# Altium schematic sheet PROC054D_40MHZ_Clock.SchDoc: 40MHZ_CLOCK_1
size 558 x 431 mm; Date: Not shown in title block; ApprovedBy: Not shown in title block; CheckedBy: Not shown in title block; Author: Not shown in title block; CompanyName: Not shown in title block; DrawnBy: a0271760; Engineer: Not shown in title block; Organization: Not shown in title block; Address1: Not shown in title block; Address2: Not shown in title block; Address3: Not shown in title block; Address4: Not shown in title block; DocumentNumber: 13; Revision: Use project pAWRameter SCH_Rev; SheetNumber: 13; SheetTotal: 19; PageSetup: Record=PageOptions¦CenterHorizontal=True¦CenterVertical=True¦PrintScale=1.00¦XCorrection=1.00¦YCorrection=1.00¦PrintKind=0¦BorderSize=5000000¦LeftOffset=0¦BottomOffset=0¦Orientation=2¦PaperLength=1000¦PaperWidth=1000¦Scale=100¦PaperSource=15¦PrintQuality=600¦MediaType=1¦DitherType=10¦PaperKind=Letter¦PrintScaleMode=1
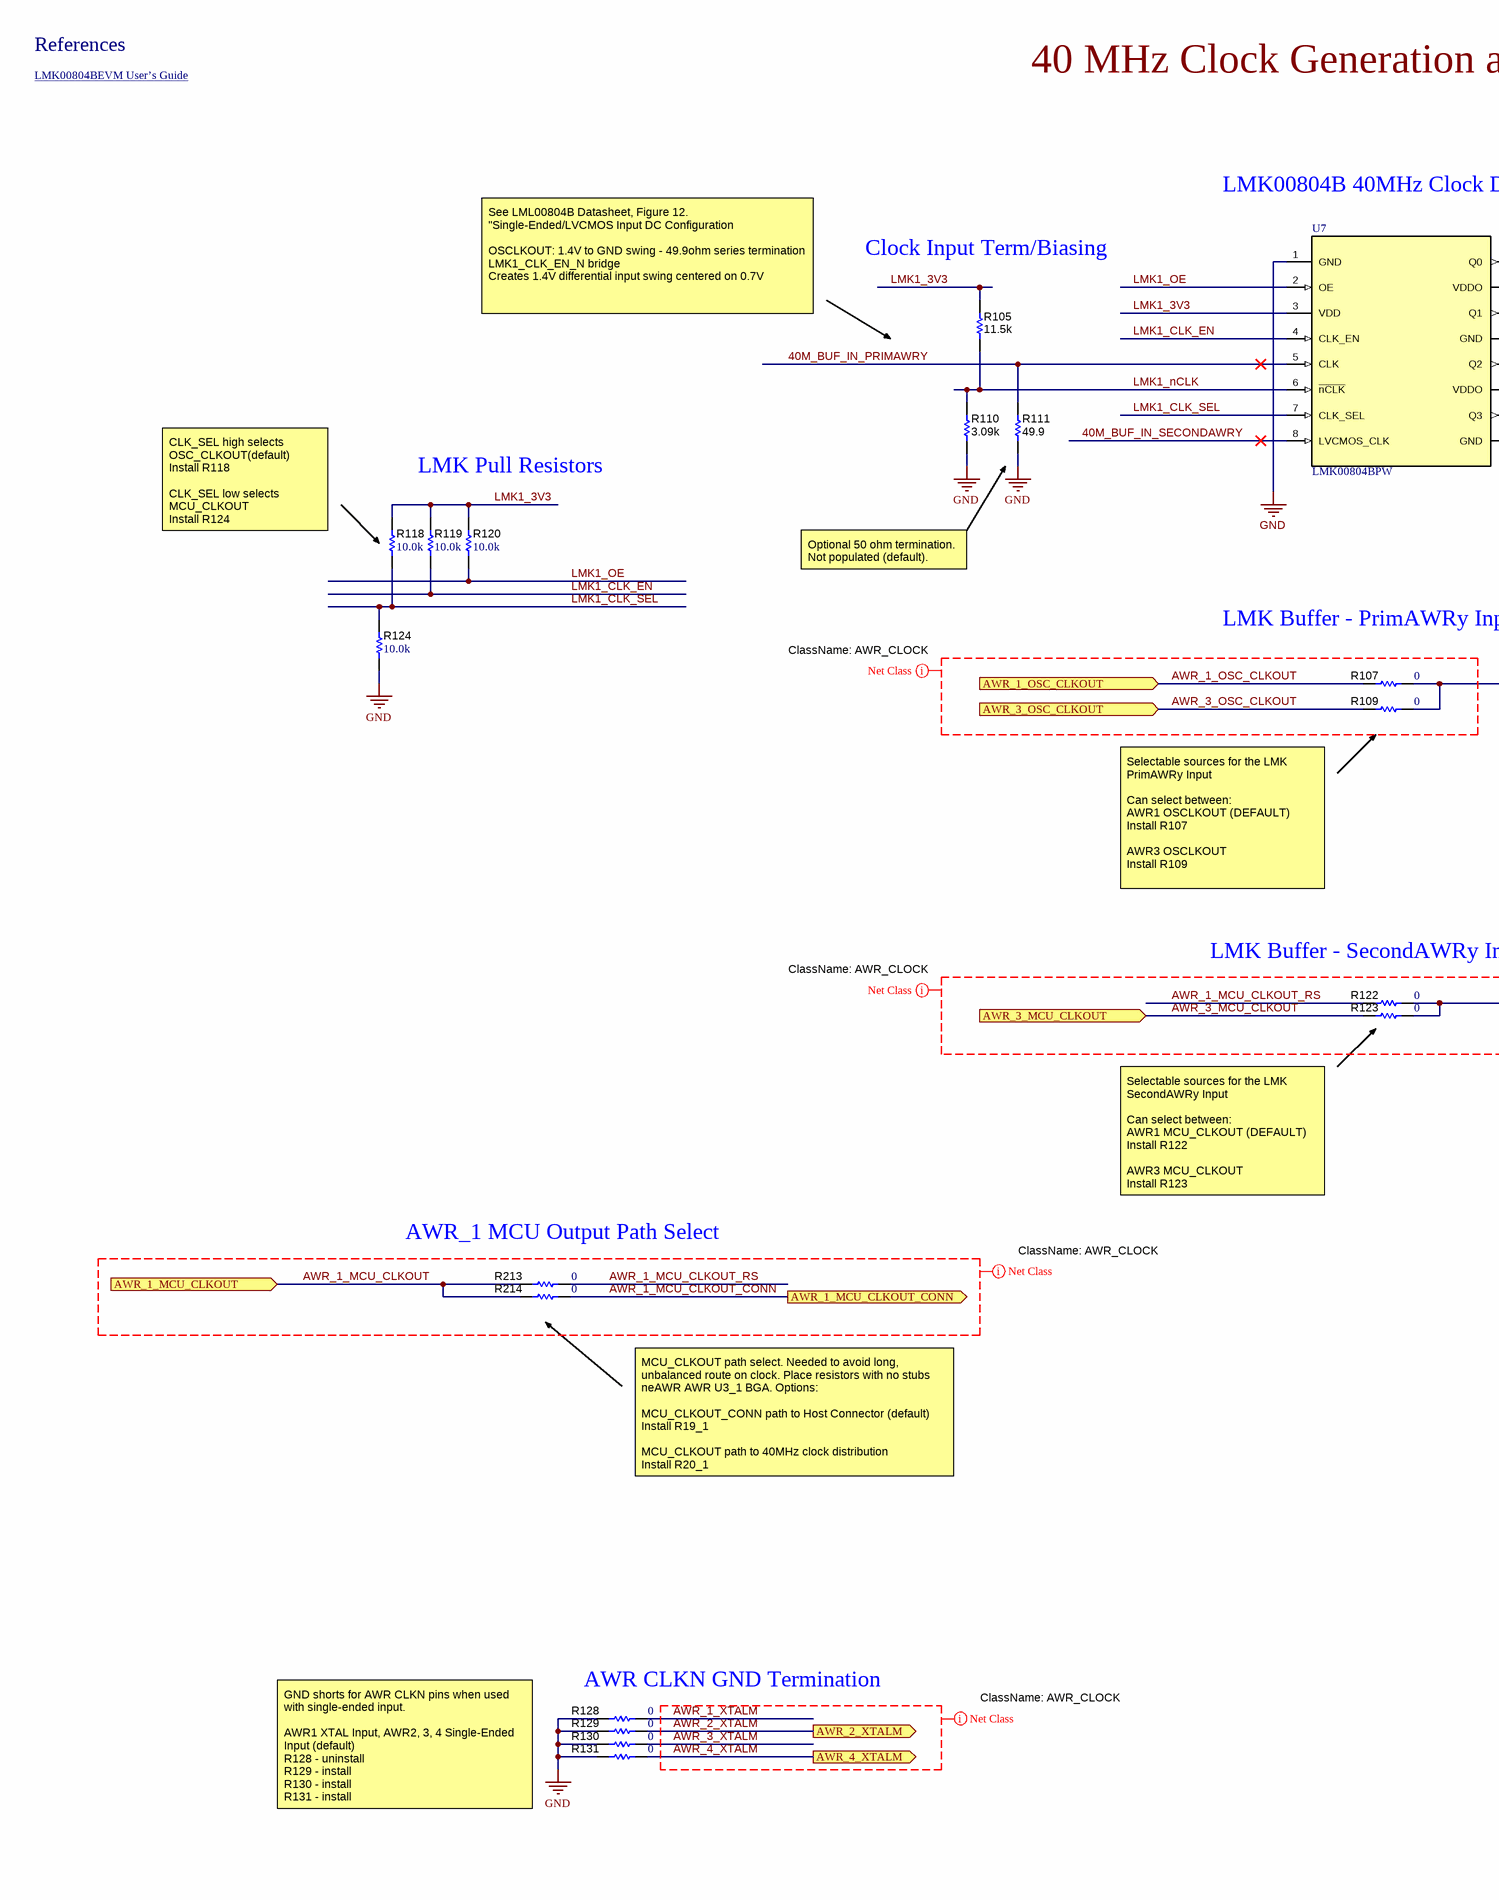
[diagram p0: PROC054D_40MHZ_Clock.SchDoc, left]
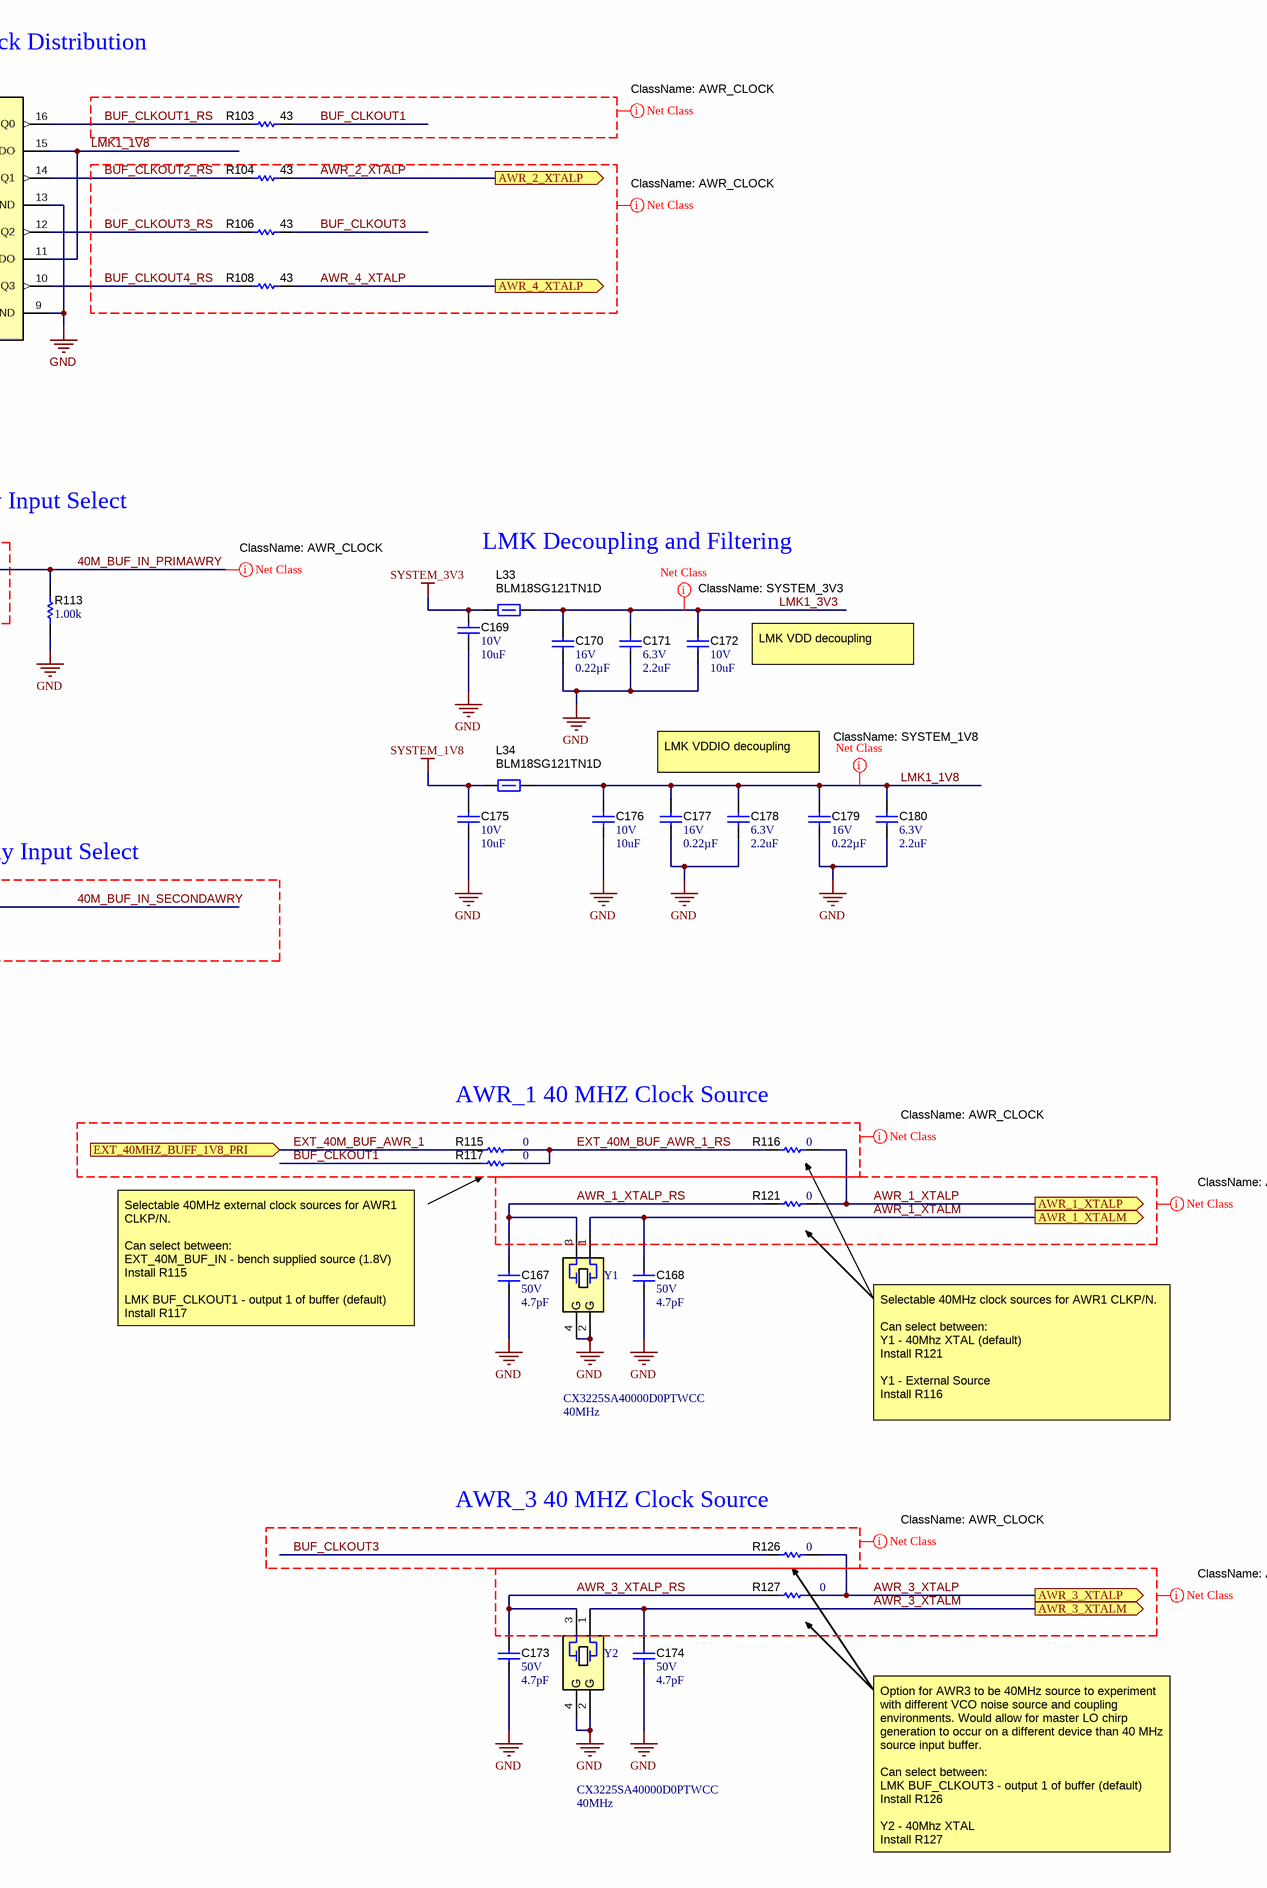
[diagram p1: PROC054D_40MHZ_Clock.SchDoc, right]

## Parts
C167  VDC_V: 50V  ValueDisplayed: 4.7pF  [0402]  (hidden comment: GJM1555C1H4R7BB01D)
C168  VDC_V: 50V  ValueDisplayed: 4.7pF  [0402]  (hidden comment: GJM1555C1H4R7BB01D)
C169  VDC_V: 10V  ValueDisplayed: 10uF  [0805_HV]  (hidden comment: GCM21BR71A106KE22L)
C170  VDC_V: 16V  ValueDisplayed: 0.22µF  [0402]  (hidden comment: GCM155R71C224KE02D)
C171  VDC_V: 6.3V  ValueDisplayed: 2.2uF  [0603]  (hidden comment: GCM188R70J225KE22D)
C172  VDC_V: 10V  ValueDisplayed: 10uF  [0805_HV]  (hidden comment: GCM21BR71A106KE22L)
C173  VDC_V: 50V  ValueDisplayed: 4.7pF  [0402]  (hidden comment: GJM1555C1H4R7BB01D)
C174  VDC_V: 50V  ValueDisplayed: 4.7pF  [0402]  (hidden comment: GJM1555C1H4R7BB01D)
C175  VDC_V: 10V  ValueDisplayed: 10uF  [0805_HV]  (hidden comment: GCM21BR71A106KE22L)
C176  VDC_V: 10V  ValueDisplayed: 10uF  [0805_HV]  (hidden comment: GCM21BR71A106KE22L)
C177  VDC_V: 16V  ValueDisplayed: 0.22µF  [0402]  (hidden comment: GCM155R71C224KE02D)
C178  VDC_V: 6.3V  ValueDisplayed: 2.2uF  [0603]  (hidden comment: GCM188R70J225KE22D)
C179  VDC_V: 16V  ValueDisplayed: 0.22µF  [0402]  (hidden comment: GCM155R71C224KE02D)
C180  VDC_V: 6.3V  ValueDisplayed: 2.2uF  [0603]  (hidden comment: GCM188R70J225KE22D)
L33  BLM18SG121TN1D  [0603]
L34  BLM18SG121TN1D  [0603]
R103  ValueDisplayed: 43  [0402]  (hidden comment: CRCW040243R0JNED)
R104  ValueDisplayed: 43  [0402]  (hidden comment: CRCW040243R0JNED)
R105  ValueDisplayed: 11.5k  [0402]  (hidden comment: ERJ-2RKF1152X)
R106  ValueDisplayed: 43  [0402]  (hidden comment: CRCW040243R0JNED)
R107  ValueDisplayed: 0  [0402]  (hidden comment: ERJ-2GE0R00X)
R108  ValueDisplayed: 43  [0402]  (hidden comment: CRCW040243R0JNED)
R109  ValueDisplayed: 0  [0402]  (hidden comment: ERJ-2GE0R00X)
R110  ValueDisplayed: 3.09k  [0402]  (hidden comment: ERJ-2RKF3091X)
R111  ValueDisplayed: 49.9  [0402]  (hidden comment: ERJ-2RKF49R9X)
R113  ValueDisplayed: 1.00k  [0402]  (hidden comment: CRCW04021K00FKED)
R115  ValueDisplayed: 0  [0402]  (hidden comment: ERJ-2GE0R00X)
R116  ValueDisplayed: 0  [0402]  (hidden comment: ERJ-2GE0R00X)
R117  ValueDisplayed: 0  [0402]  (hidden comment: ERJ-2GE0R00X)
R118  ValueDisplayed: 10.0k  [0402]  (hidden comment: CRCW040210K0FKED)
R119  ValueDisplayed: 10.0k  [0402]  (hidden comment: CRCW040210K0FKED)
R120  ValueDisplayed: 10.0k  [0402]  (hidden comment: CRCW040210K0FKED)
R121  ValueDisplayed: 0  [0402]  (hidden comment: ERJ-2GE0R00X)
R122  ValueDisplayed: 0  [0402]  (hidden comment: ERJ-2GE0R00X)
R123  ValueDisplayed: 0  [0402]  (hidden comment: ERJ-2GE0R00X)
R124  ValueDisplayed: 10.0k  [0402]  (hidden comment: CRCW040210K0FKED)
R126  ValueDisplayed: 0  [0402]  (hidden comment: ERJ-2GE0R00X)
R127  ValueDisplayed: 0  [0201]  (hidden comment: CRCW02010000Z0ED)
R128  ValueDisplayed: 0  [0402]  (hidden comment: ERJ-2GE0R00X)
R129  ValueDisplayed: 0  [0402]  (hidden comment: ERJ-2GE0R00X)
R130  ValueDisplayed: 0  [0402]  (hidden comment: ERJ-2GE0R00X)
R131  ValueDisplayed: 0  [0402]  (hidden comment: ERJ-2GE0R00X)
R213  ValueDisplayed: 0  [0402S]  (hidden comment: ERJ-2GE0R00X)
R214  ValueDisplayed: 0  [0402S]  (hidden comment: ERJ-2GE0R00X)
U7  LMK00804BPW  [PW0016A_N]
Y1  Frequency_Fixed: 40MHz  [Kyocera_CX3225SA]  (hidden comment: CX3225SA40000D0PTWCC)
Y2  Frequency_Fixed: 40MHz  [Kyocera_CX3225SA]  (hidden comment: CX3225SA40000D0PTWCC)

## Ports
AWR_1_MCU_CLKOUT (in), AWR_1_MCU_CLKOUT_CONN (out), AWR_1_OSC_CLKOUT (in), AWR_1_XTALM (out), AWR_1_XTALP (out), AWR_2_XTALM (out), AWR_2_XTALP (out), AWR_3_MCU_CLKOUT (in), AWR_3_OSC_CLKOUT (in), AWR_3_XTALM (out), AWR_3_XTALP (out), AWR_4_XTALM (out), AWR_4_XTALP (out), EXT_40MHZ_BUFF_1V8_PRI (in)

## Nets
GND: C167.2 C168.1 C169.2 C170.2 C171.1 C172.2 C173.2 C174.2 C175.2 C176.2 C177.2 C178.1 C179.2 C180.1 R110.1 R111.1 R113.1 R124.1 R128.2 R129.1 R130.1 R131.1 U7.1(GND) U7.9(GND) U7.13(GND) Y1.2(GND) Y1.4(GND) Y2.2(GND) Y2.4(GND)
SYSTEM_1V8: C175.1 L34.1
SYSTEM_3V3: C169.1 L33.1
40M_BUF_IN_PRIMAWRY: R107.2 R109.2 R111.2 R113.2 U7.5(CLK)
40M_BUF_IN_SECONDAWRY: R122.2 R123.2 U7.8(LVCMOS_CLK)
AWR_1_MCU_CLKOUT: R213.1 R214.1 ; port AWR_1_MCU_CLKOUT
AWR_1_MCU_CLKOUT_CONN: R214.2 ; port AWR_1_MCU_CLKOUT_CONN
AWR_1_MCU_CLKOUT_RS: R122.1 R213.2
AWR_1_OSC_CLKOUT: R107.1 ; port AWR_1_OSC_CLKOUT
AWR_1_XTALM: C168.2 R128.1 Y1.1 ; port AWR_1_XTALM
AWR_1_XTALP: R116.2 R121.2 ; port AWR_1_XTALP
AWR_1_XTALP_RS: C167.1 R121.1 Y1.3
AWR_2_XTALM: R129.2 ; port AWR_2_XTALM
AWR_2_XTALP: R104.2 ; port AWR_2_XTALP
AWR_3_MCU_CLKOUT: R123.1 ; port AWR_3_MCU_CLKOUT
AWR_3_OSC_CLKOUT: R109.1 ; port AWR_3_OSC_CLKOUT
AWR_3_XTALM: C174.1 R130.2 Y2.1 ; port AWR_3_XTALM
AWR_3_XTALP: R126.2 R127.2 ; port AWR_3_XTALP
AWR_3_XTALP_RS: C173.1 R127.1 Y2.3
AWR_4_XTALM: R131.2 ; port AWR_4_XTALM
AWR_4_XTALP: R108.2 ; port AWR_4_XTALP
BUF_CLKOUT1: R103.2 R117.1
BUF_CLKOUT1_RS: R103.1 U7.16(Q0)
BUF_CLKOUT2_RS: R104.1 U7.14(Q1)
BUF_CLKOUT3: R106.2 R126.1
BUF_CLKOUT3_RS: R106.1 U7.12(Q2)
BUF_CLKOUT4_RS: R108.1 U7.10(Q3)
EXT_40M_BUF_AWR_1: R115.1 ; port EXT_40MHZ_BUFF_1V8_PRI
EXT_40M_BUF_AWR_1_RS: R115.2 R116.1 R117.2
LMK1_1V8: C176.1 C177.1 C178.2 C179.1 C180.2 L34.2 U7.11(VDDO) U7.15(VDDO)
LMK1_3V3: C170.1 C171.2 C172.1 L33.2 R105.2 R118.2 R119.2 R120.2 U7.3(VDD)
LMK1_CLK_EN: R119.1 U7.4(CLK_EN)
LMK1_CLK_SEL: R118.1 R124.2 U7.7(CLK_SEL)
LMK1_nCLK: R105.1 R110.2 U7.6(~{nCLK})
LMK1_OE: R120.1 U7.2(OE)

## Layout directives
net class SYSTEM_3V3: LMK1_3V3
net class SYSTEM_1V8: LMK1_1V8
net class AWR_CLOCK: 40M_BUF_IN_PRIMAWRY, 40M_BUF_IN_SECONDAWRY, AWR_1_MCU_CLKOUT, AWR_1_MCU_CLKOUT_CONN, AWR_1_MCU_CLKOUT_RS, AWR_1_OSC_CLKOUT, AWR_1_XTALM, AWR_1_XTALP, AWR_1_XTALP_RS, AWR_2_XTALM, AWR_2_XTALP, AWR_3_MCU_CLKOUT, AWR_3_OSC_CLKOUT, AWR_3_XTALM, AWR_3_XTALP, AWR_3_XTALP_RS, AWR_4_XTALM, AWR_4_XTALP, BUF_CLKOUT1, BUF_CLKOUT1_RS, BUF_CLKOUT2_RS, BUF_CLKOUT3, BUF_CLKOUT3_RS, BUF_CLKOUT4_RS, EXT_40M_BUF_AWR_1, EXT_40M_BUF_AWR_1_RS

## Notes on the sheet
- References
- LMK00804BEVM User’s Guide <http://www.ti.com/lit/ug/snou129/snou129.pdf>
- 40 MHz Clock Generation and Distribution
- LMK00804B 40MHz Clock Distribution
- Clock Input Term/Biasing
- See LML00804B Datasheet, Figure 12. "Single-Ended/LVCMOS Input DC Configuration
  OSCLKOUT: 1.4V to GND swing - 49.9ohm series termination
  LMK1_CLK_EN_N bridge
  Creates 1.4V differential input swing centered on 0.7V
- LMK Pull Resistors
- CLK_SEL high selects
  OSC_CLKOUT(default)
  Install R118
  CLK_SEL low selects
  MCU_CLKOUT
  Install R124
- Optional 50 ohm termination.
  Not populated (default).
- LMK Buffer - PrimAWRy Input Select
- LMK Decoupling and Filtering
- LMK VDD decoupling
- Selectable sources for the LMK PrimAWRy Input
  Can select between:
  AWR1 OSCLKOUT (DEFAULT)
  Install R107
  AWR3 OSCLKOUT
  Install R109
- LMK VDDIO decoupling
- LMK Buffer - SecondAWRy Input Select
- Selectable sources for the LMK SecondAWRy Input
  Can select between:
  AWR1 MCU_CLKOUT (DEFAULT)
  Install R122
  AWR3 MCU_CLKOUT
  Install R123
- AWR_1 40 MHZ Clock Source
- AWR_1 MCU Output Path Select
- Selectable 40MHz external clock sources for AWR1 CLKP/N.
  Can select between:
  EXT_40M_BUF_IN - bench supplied source (1.8V)
  Install R115
  LMK BUF_CLKOUT1 - output 1 of buffer (default)
  Install R117
- MCU_CLKOUT path select. Needed to avoid long, unbalanced route on clock. Place resistors with no stubs neAWR AWR U3_1 BGA. Options:
  MCU_CLKOUT_CONN path to Host Connector (default)
  Install R19_1
  MCU_CLKOUT path to 40MHz clock distribution
  Install R20_1
- Selectable 40MHz clock sources for AWR1 CLKP/N.
  Can select between:
  Y1 - 40Mhz XTAL (default)
  Install R121
  Y1 - External Source
  Install R116
- (near R126) AWR_3 40 MHZ Clock Source
- AWR CLKN GND Termination
- GND shorts for AWR CLKN pins when used with single-ended input.
  AWR1 XTAL Input, AWR2, 3, 4 Single-Ended Input (default)
  R128 - uninstall
  R129 - install
  R130 - install
  R131 - install
- Option for AWR3 to be 40MHz source to experiment with different VCO noise source and coupling environments. Would allow for master LO chirp generation to occur on a different device than 40 MHz source input buffer.
  Can select between:
  LMK BUF_CLKOUT3 - output 1 of buffer (default)
  Install R126
  Y2 - 40Mhz XTAL
  Install R127

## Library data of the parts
C167 C168 C173 C174 = CMP-0006367-2: CAP, CERM, 4.7 pF, 50 V, +/- 2%, C0G/NP0, 0402; Manufacturer: MuRata; TaMin_C: -55°C; Polarized: N; SizeAreaWB_mm2: 3; Value1: Unknown; U/M: EA; Value: 4.7pF; TaMax_C: 125°C; SizeZ_mm: 0.6; SizeX_mm: 1; SizeY_mm: 0.5; AEC Category: Q200
C169 C172 C175 C176 = CMP-0008017-2: CAP, CERM, 10 uF, 10 V, +/- 10%, X7R, 0805; Manufacturer: MuRata; TaMin_C: -55°C; Polarized: N; SizeAreaWB_mm2: 6.75; Value1: Unknown; U/M: EA; Value: 10uF; TaMax_C: 125°C; SizeZ_mm: 1.45; SizeX_mm: 2; SizeY_mm: 1.25; Cap_Case: 0805; SizeArea_mm2: 2.5; CompType: Capacitor; Cap_F: 10µF; AEC Category: Q200
C170 C177 C179 = CMP-0078265-1: CAP, CERM, 0.22 µF, 16 V,+/- 10%, X7R, AEC-Q200 Grade 1, 0402; Manufacturer: MuRata; TaMin_C: -55°C; Polarized: N; SizeAreaWB_mm2: 3; U/M: EA; Value: 0.22uF; TaMax_C: 125°C; SizeZ_mm: 0.6; SizeX_mm: 1; SizeY_mm: 0.5; CompType: Capacitor; AEC Qualified: Y; Cap_F: 220nF; AEC Category: Q200
C171 C178 C180 = CMP-0007134-5: CAP, CERM, 2.2 uF, 6.3 V, +/- 10%, X7R, AEC-Q200 Grade 1, 0603; Manufacturer: MuRata; TaMin_C: -55°C; Polarized: N; SizeAreaWB_mm2: 4.68; Value1: Unknown; U/M: EA; Value: 2.2uF; TaMax_C: 125°C; SizeZ_mm: 1; SizeX_mm: 1.6; SizeY_mm: 0.8; SizeArea_mm2: 1.28; AEC Qualified: Y; Cap_F: 2.2µF; AEC Category: Q200
L33 L34 = CMP-0003352-2: Ferrite Bead, 120 ohm @ 100 MHz, 3 A, 0603; Manufacturer: MuRata; ZTyp@100MHz_Ohm: 120; SizeAreaWB_mm2: 4.68; DCR_ohm: 0.025; Value1: 0.025 ohm; Value: 120 ohm; Imax_A: 3A; SizeZ_mm: 1; SizeX_mm: 1.6; SizeY_mm: 0.8; SizeArea_mm2: 1.28
R103 R104 R106 R108 = CMP-0026932-3: RES, 43, 5%, 0.063 W, AEC-Q200 Grade 0, 0402; Manufacturer: Vishay-Dale; Power_W: 63mW; TempCo: 200 ppm/C; Value_Code: 43R0; Value: 43; EIA_Code: E24; SizeX_mm: 1; SizeY_mm: 0.5; SizeZ_mm: 0.6; Value2: 0.063W; AEC Qualified: Y; VDC_V: 50V; AEC Category: Q200; AEC Grade: 0
R105 = CMP-0082348-1: RES, 11.5 k, 1%, 0.1 W, AEC-Q200 Grade 0, 0402; Manufacturer: Panasonic; Value_Code: 11k5; SizeAreaWB_mm2: 3; SizeArea_mm2: 0.5; AEC Qualified: Y; AEC Category: Q200; Value: 11.5k; SizeZ_mm: 0.6; EIA_Code: E96; TempCo: 100 ppm/C; AEC Grade: 0; Power_W: 100mW; Value2: 0.1W; SizeX_mm: 1
R107 R109 R117 R122 R123 R129-R131 R213 R214 = CMP-0026992-3: RES, 0, 5%, 0.1 W, AEC-Q200 Grade 0, 0402; Manufacturer: Panasonic; Power_W: 100mW; TempCo: 600 ppm/C; Value_Code: 0000; Value: 0; EIA_Code: E24; SizeX_mm: 1; SizeY_mm: 0.5; SizeZ_mm: 0.6; Value2: 0.1W; AEC Qualified: Y; VDC_V: 50V; AEC Category: Q200; SizeAreaWB_mm2: 3
R110 = CMP-0082349-1: RES, 3.09 k, 1%, 0.1 W, AEC-Q200 Grade 0, 0402; Manufacturer: Panasonic; Value_Code: 3k09; SizeAreaWB_mm2: 3; SizeArea_mm2: 0.5; AEC Qualified: Y; AEC Category: Q200; Value: 3.09k; SizeZ_mm: 0.6; Green_REACh: Incomplete; EIA_Code: E96; TempCo: 100 ppm/C; AEC Grade: 0; Power_W: 100mW; Value2: 0.1W; Green_Lifecycle: Active; SizeX_mm: 1
R111 = CMP-0026703-1: RES, 49.9, 1%, 0.1 W, AEC-Q200 Grade 0, 0402; Manufacturer: Panasonic; Power_W: 100mW; TempCo: 100 ppm/C; Value_Code: 49R9; U/M: EA; Value: 49.9; EIA_Code: E96; SizeX_mm: 1; SizeY_mm: 0.5; SizeZ_mm: 0.6; Value2: 0.1W; AEC Qualified: Y; VDC_V: 50V; AEC Grade: 0; AEC Category: Q200
R113 = CMP-0026071-3: RES, 1.00 k, 1%, 0.063 W, AEC-Q200 Grade 0, 0402; Manufacturer: Vishay-Dale; Power_W: 63mW; TempCo: 100 ppm/C; Value_Code: 1k00; Value: 1.00k; EIA_Code: E96; Res_ohm: 1k; SizeX_mm: 1; SizeY_mm: 0.5; SizeZ_mm: 0.6; Value2: 0.063W; AEC Qualified: Y; VDC_V: 50V; AEC Category: Q200; AEC Grade: 0
R115 R116 R121 R126 R128 = CMP-0026992-3: RES, 0, 5%, 0.1 W, AEC-Q200 Grade 0, 0402; Manufacturer: Panasonic; Power_W: 100mW; TempCo: 600 ppm/C; Value_Code: 0000; Value: 0; EIA_Code: E24; SizeX_mm: 1; SizeY_mm: 0.5; SizeZ_mm: 0.6; Value2: 0.1W; CompType: Resistor; AEC Qualified: Y; VDC_V: 50V; AEC Category: Q200; SizeAreaWB_mm2: 3
R118-R120 R124 = CMP-0025958-3: RES, 10.0 k, 1%, 0.063 W, AEC-Q200 Grade 0, 0402; Manufacturer: Vishay-Dale; Power_W: 63mW; TempCo: 100 ppm/C; Value_Code: 10k0; Value: 10.0k; EIA_Code: E96; Res_ohm: 10k; SizeX_mm: 1; SizeY_mm: 0.5; SizeZ_mm: 0.6; Value2: 0.063W; AEC Qualified: Y; VDC_V: 50V; AEC Category: Q200; AEC Grade: 0
R127 = CMP-0027008-4: RES, 0, 5%, 0.05 W, 0201; Manufacturer: Vishay-Dale; Power_W: 50mW; TempCo: ppm/C; Value_Code: 0000; Value: 0; EIA_Code: E24; SizeX_mm: 0.6; SizeY_mm: 0.3; SizeZ_mm: 0.26; Value2: 0.05W; SizeArea_mm2: 0.18; AEC Qualified: N; AEC Category: Q200
U7 = CMP-0065663-1: Low Skew, 1-to-4 Multiplexed Differential/LVCMOS-to-LVCMOS/TTL Fanout Buffer, PW0016A (TSSOP-16); Alternate Manufacturer: Texas Instruments; Green_Lifecycle: Active; SizeAreaWB_mm2: 58.8; Green_REACh: Passed; U/M: EA; SizeZ_mm: 1.2; SizeX_mm: 6.4; SizeY_mm: 5.0; SizeArea_mm2: 32.0; CompType: IC
Y1 Y2 = CMP-0004694-3: Crystal, 40 MHz, 8pF, SMD; Manufacturer: Kyocera; TaMin_C: -40°C; Frequency Stability: +/-200ppm; SizeAreaWB_mm2: 14.7; TaMax_C: 125°C; SizeZ_mm: 0.8; SizeX_mm: 2.5; SizeY_mm: 3.2; SizeArea_mm2: 8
